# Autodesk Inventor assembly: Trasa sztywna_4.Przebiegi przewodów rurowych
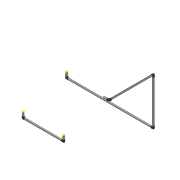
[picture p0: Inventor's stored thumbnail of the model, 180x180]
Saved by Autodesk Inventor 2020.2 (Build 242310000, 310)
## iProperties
ActiveState: False
BendRadius: UnInitValue
CouplingKey: v3#7e56b2cb-a132-4546-b8a7-a14538454b94#3
DefaultBendRadius: UnInitValue
Diameter: 1/2
DiameterType: Nominal
Elbow45Key: v3#a96c5204-26e4-4bb2-b8f1-f0623fbc94bb#2
Elbow90Key: v3#b72bb08b-ad33-47cc-a03d-7f3d76c6616b#3
ElbowCustomKey: UnInitValue
EndFittingKey: UnInitValue
Ending: UnInitValue
FittingMaterial: UnInitValue
FittingStandard: UnInitValue
FlangeKey: UnInitValue
Gap: UnInitValue
GasketKey: UnInitValue
ID: UnInitValue
IntermediateSegmentsInc: 2,540 mm
IntermediateSegmentsMax: 5080,000 mm
IntermediateSegmentsMin: 50,800 mm
IsButtWelded: False
IsFlanged: False
IsSelfDraining: False
Material: UnInitValue
MixedUnits: False
Name: ISO 7598/ISO 49 - Rury stalowe gwintowane ze stalowymi łącznikami
OD: UnInitValue
PipeKey: v3#1052637f-74b5-47f4-adeb-d4e8d3fa53b8#1
PipeType: Rigid Pipe
PipingComponentColor: As Material
RoundUpValue: UnInitValue
RouteDirection45: True
RouteDirection90: True
Schedule: ID=16.1
ShowGap: UnInitValue
Standard: UnInitValue
StartFittingKey: UnInitValue
SuppressEndFitting: UnInitValue
SuppressStartFitting: UnInitValue
TerminationSegmentsInc: 2,540 mm
TerminationSegmentsMax: 5080,000 mm
TerminationSegmentsMin: 50,800 mm
UseFlangsForCouplings: UnInitValue
UseSubASM: UnInitValue
_ComponentInfo: <CS><C N="Pipe" R="1.065000" IR="0.805000" PL="PL" PN="ISO 7598 Tube with Threaded Ends DN15"><CO N="1"><FE V="0"/><FD V="1"/><ET V="Threaded"/><NS V="1/2"/><MA
CouplingKey: UnInitValue
Diameter: 6
Elbow90Key: v3#97ecdcaf-8aa3-4fb0-8b6a-3da783de2ad5#108
Gap: 1,575 mm
IntermediateSegmentsInc: 0.00001 in
IntermediateSegmentsMin: 76,200 mm
IsButtWelded: True
Name: ASTM A 53/A-ASME B16.9 - Rura stalowa ze szwem
PipeKey: v3#4ce5e9fa-6da0-4801-ac02-ee7a0fb518d6#77
RouteDirection45: False
Schedule: 40
ShowGap: True
TerminationSegmentsInc: 0.00001 in
TerminationSegmentsMin: 76,200 mm
_ComponentInfo: <CS><C N="Elbow90" ER="15.240000" S1="15.240000" S2="15.240000" D1="0.000000" D2="0.000000" PartType="fitting" SymKey="ELBW"><CO N="1"><FE V="2"/><FD V="0"/><ET
Angle: UnInitValue
BendRadius: 12,700 mm
Elbow45Key: UnInitValue
Elbow90Key: UnInitValue
ID: 1,27
IntermediateSegmentsInc: UnInitValue
IntermediateSegmentsMax: UnInitValue
IntermediateSegmentsMin: UnInitValue
IsButtWelded: UnInitValue
IsFlanged: UnInitValue
IsSelfDraining: UnInitValue
MixedUnits: UnInitValue
Name: Przewód hydrauliczny – bez złączek
OD: 2,2352
PipeKey: v3#d489867e-ac9b-47ea-b952-0a1b885f66be#4
PipeType: Flexible Hose
RoundUpValue: 3,175 mm
RouteDirection45: UnInitValue
RouteDirection90: UnInitValue
Schedule: ID=0.5
SuppressEndFitting: True
SuppressStartFitting: True
TerminationSegmentsInc: UnInitValue
TerminationSegmentsMax: UnInitValue
TerminationSegmentsMin: UnInitValue
UseSubASM: True
_ComponentInfo: <CS><C N="Pipe" R="1.117600" OR="1.117600" IR="0.635000" PL="PL" PartType="" SymKey="" PN="Parker Hydraulic Hose - No Skive 1/2"><CO N="1"><FE V="0"/><FD V="0"/
Diameter: M40
Elbow45Key: v3#97879d80-057e-491b-840b-74a9b3a7cf63#17
Elbow90Key: v3#ace818b0-7b7c-4ad9-b19c-6da358a202c1#17
IntermediateSegmentsInc: 1,000 mm
IntermediateSegmentsMax: 5000,000 mm
IntermediateSegmentsMin: 60,000 mm
Name: DIN 2458/DIN 2605 - Rury stalowe spawane i łączniki
PipeKey: v3#dcef2839-8903-4c98-a96c-b861f5d9bb7f#98
Schedule: ID=30.7
TerminationSegmentsInc: 1,000 mm
TerminationSegmentsMax: 5000,000 mm
TerminationSegmentsMin: 60,000 mm
_ComponentInfo: <CS><C N="Pipe" R="2.415000" IR="1.535000" PL="PL" PN="DIN 2458 Pipe 48.3 x 8.8"><CO N="1"><FE V="2"/><FD V="0"/><ET V="Welded"/><NS V="M40"/><MA V="0.000000"/>
USE_R9_BOM: False
Angle: 92,00 deg
Diameter: 1
Elbow45Key: v3#bf26aa2a-f3dd-474c-8758-922a145c2b02#15
Elbow90Key: v3#3e93288f-9bb7-4e46-9d6b-544f8c20ca1c#3
ElbowCustomKey: v3#1f3bd44a-47ab-42f9-b3e0-74afa0c3f0ca#3
Gap: 2,388 mm
IsSelfDraining: True
Name: ASME BPE - Rura stalowa kołnierzowa
PipeKey: v3#b10c956f-6fc6-429e-8056-0864a8581764#35
Schedule: ID=0.87
_ComponentInfo: <CS><C N="Pipe" R="1.270000" OR="1.270000" IR="1.104900" PL="PL" PartType="pipe" SymKey="" PN="ASTM A 269 Tube with Welded ends 1 x 0.87"><CO N="1"><FE V="2"/><
CouplingKey: v3#181262db-c004-4877-bc40-c64b931a44f6#3
Elbow45Key: v3#960407aa-00b9-4d72-aae7-d50595845cfd#3
Elbow90Key: v3#6c92b367-65e9-486b-b952-db434ae2548d#3
IntermediateSegmentsMin: 20,000 mm
Name: JIS G 3442/JIS B 2301 - Rury stalowe gwintowane ze stalowymi łącznikami
PipeKey: v3#9964fba4-9d5a-4d75-85a8-e38022ccdce1#2
TerminationSegmentsMin: 20,000 mm
_ComponentInfo: <CS><C N="Pipe" R="1.085000" IR="0.805000" PL="PL" PN="JIS G 3442 Pipe with Threaded Ends 21.7 x 2.8"><CO N="1"><FE V="0"/><FD V="1"/><ET V="Threaded"/><NS V="1
EndFittingKey: v3#cc3bd835-95a2-497d-9893-176cd9c426f6#7
Name: Przewód hydrauliczny – gwint stożkowy wewnętrzny
StartFittingKey: v3#cc3bd835-95a2-497d-9893-176cd9c426f6#7
SuppressEndFitting: False
SuppressStartFitting: False
CouplingKey: v3#3edf83e2-464b-4b31-84c5-c329ffbf2a4f#5
Elbow45Key: v3#2f597a97-b15b-49d4-87cb-7bfe69eb62ee#5
Elbow90Key: v3#fbd68fd5-590c-4cb5-8c20-9e9bdd396a04#5
Name: DIN 8062/DIN 8063 - Rury i złączki PCV-U
PipeKey: v3#3d294dc7-89c3-4c37-a0ae-28c15a73bfd0#13
Schedule: 5
_ComponentInfo: <CS><C N="Pipe" R="2.000000" IR="1.700000" PL="PL" PN="DIN 8062 Pipe 40 x 3"><CO N="1"><FE V="0"/><FD V="0"/><ET V="Jointed"/><NS V="M40"/><MA V="8.000000"/><MI
CouplingKey: v3#52ad3977-2b89-4007-a6a6-7626bac0ae85#4
Elbow45Key: v3#5c2ab816-abcb-49a6-a106-4733af000f51#4
Elbow90Key: v3#160eac10-3e6f-4b5c-839c-61eee0d373dc#4
Name: ASME B36.10M-ASME B16.11 - Rury stalowe gwintowane
PipeKey: v3#4a736116-503a-44ad-a922-868ac6b46736#1
Schedule: 30
_ComponentInfo: <CS><C N="Pipe" R="1.066800" IR="0.825500" PL="PL" PN="ASME B36.10M Pipe with Threaded Ends 1/2 - Schedule 30"><CO N="1"><FE V="0"/><FD V="1"/><ET V="Threaded"/
Manager: www.cadconsulting.pl
Company: Fabian Stasiak CAD Consulting
CouplingKey: v3#eaa8de87-dc67-4eca-ba7e-4267a30f8f7f#2
Elbow45Key: v3#2769403e-a4fd-4a4c-8e4c-659ea845bd78#2
Elbow90Key: v3#c4513a61-3106-4a78-baf9-a1badd100245#2
IntermediateSegmentsMax: 2500,000 mm
Name: JIS K 6741/JIS K 6739 - Rury i złączki PCV-U
PipeKey: v3#45338dd0-af69-48c0-a2ed-8ade33a08701#5
Schedule: VP
TerminationSegmentsMax: 2500,000 mm
_ComponentInfo: <CS><C N="Pipe" R="2.400000" IR="2.040000" PL="PL" PN="JIS K 6741 Pipe VP 40"><CO N="1"><FE V="0"/><FD V="1"/><ET V="Jointed"/><NS V="M40"/><MA V="4.000000"/><M
EndFittingKey: v3#c5e461f5-5e73-4f2e-8c1e-4358d4d6f46c#4
Name: Przewód hydrauliczny – gwint wewnętrzny - obrotowy
StartFittingKey: v3#c5e461f5-5e73-4f2e-8c1e-4358d4d6f46c#4
EndFittingKey: v3#b50cb43e-68c0-48ac-8e25-7ef224ce0e6c#3
Name: Przewód hydrauliczny – gwint zewnętrzny prosty
StartFittingKey: v3#b50cb43e-68c0-48ac-8e25-7ef224ce0e6c#3
CouplingKey: v3#ed415c76-4cec-44a3-ba67-72e47bf70384#4
Elbow45Key: v3#2e5fd082-3851-4eb0-bde1-6c7078a7d72b#4
Elbow90Key: v3#82a08401-12d7-413b-b7f9-9cf3b607be7b#4
IntermediateSegmentsMin: 25,400 mm
Name: ASTM A53/A53M-ASME B16.11 - Rury stalowe spawane
PipeKey: v3#4ce5e9fa-6da0-4801-ac02-ee7a0fb518d6#7
TerminationSegmentsMin: 25,400 mm
_ComponentInfo: <CS><C N="Pipe" R="1.066800" IR="0.789940" PL="PL" PN="ASTM A 53/A 53M Pipe 1/2 - Schedule 40"><CO N="1"><FE V="0"/><FD V="0"/><ET V="Welded"/><NS V="1/2"/><MA 
ActiveState: True
CouplingKey: v3#12b64993-10e6-4915-8315-0c0cce209ad0#8
Elbow45Key: v3#28e76e79-e22c-40ab-8be2-ff545b1407c5#8
Elbow90Key: v3#1f65ece3-c41a-48d4-8661-909ed34ade86#8
Name: JIS G 3458/JIS B 2316 - Rury stalowe spawane i łączniki
PipeKey: v3#da14b0ab-0b36-4851-8d66-8c9cd0bcbe86#23
Schedule: 80
_ComponentInfo: <CS><C N="Pipe" R="2.430000" IR="1.920000" PL="PL" PN="JIS G 3458 Pipe 40 A x Sch 80"><CO N="1"><FE V="0"/><FD V="1"/><ET V="Welded"/><NS V="M40"/><MA V="0.0000
EndFittingKey: v3#933069c9-73b6-4141-af99-628d4a97b2c2#1
Name: Przewód hydrauliczny – złączki kołnierzowe SAE
StartFittingKey: v3#933069c9-73b6-4141-af99-628d4a97b2c2#1
Elbow90Key: v3#6a678020-d9d9-4685-bba9-906b9a167083#10
FlangeKey: v3#24991861-26e3-4c21-a713-f46e314eddd5#10
GasketKey: v3#2a41914c-f5fb-4682-9c6a-1870d826d3d0#23
IsFlanged: True
Name: ASTM A 53/A 53M - Rura stalowa kołnierzowa/spawana doczołowo
UseFlangsForCouplings: False
_ComponentInfo: <CS><C N="Pipe" R="8.413750" OR="8.413750" IR="7.702550" PL="PL" PartType="pipe" SymKey="" PN="ASTM A 53/A 53M Pipe 6 - Schedule 40"><CO N="1"><FE V="2"/><FD V=
Created: 2014-08
Part Number: Trasa sztywna_4.Przebiegi przewodów rurowych
Document SubType Name: Tube & Pipe
Designer: F.Stasiak
Manufacturer: Standard
Standards Organization: Custom
Catalog Web Link: www.expertbooks.pl
EndFittingKey: v3#c8250148-a7b6-458b-b7bd-3b56763ca7cc#13
Name: Przewód hydrauliczny – gwint stożkowy zewnętrzny
StartFittingKey: v3#c8250148-a7b6-458b-b7bd-3b56763ca7cc#13
FlangeKey: v3#c11442d2-c568-438f-a870-8ac9b5b636cb#10
Name: ASTM A 53/A-ASME B16.5 - Rura stalowa gwintowana kołnierzowa
PipeKey: v3#c5bd7d28-cdb3-4507-9f3d-c2787d93fe8a#40
_ComponentInfo: <CS><C N="Elbow90" ER="21.590000" S1="21.590000" S2="21.590000" D1="0.000000" D2="0.000000" PartType="fitting" SymKey="ELFL"><CO N="1"><FE V="2"/><FD V="1"/><ET
CouplingKey: v3#b06656e5-2b55-488c-bcf0-6a90c79c4683#2
Elbow45Key: v3#421a8b99-1721-409a-bc3b-c00889561754#1
Elbow90Key: v3#17490b17-1dd8-40fc-8de7-1a70c3bab2d7#1
IntermediateSegmentsMax: 2540,000 mm
Name: ISO 4065-ISO 3633 - Rury i złączki PCV
PipeKey: v3#4f84f716-5ba0-45ef-967a-c32c3d7345ce#70
Schedule: S40
TerminationSegmentsMax: 2540,000 mm
_ComponentInfo: <CS><C N="Pipe" R="2.000000" IR="1.950000" PL="PL" PN="ISO 4065 Pipe 40 x 0.5 S40"><CO N="1"><FE V="0"/><FD V="0"/><ET V="Jointed"/><NS V="M40"/><MA V="6.000000
CouplingKey: v3#771d4942-b9e7-43bc-9d41-ab12a9580492#3
Elbow45Key: v3#626cc28c-1a24-4045-be0d-40d896dc828d#3
Elbow90Key: v3#bc6b44ab-9235-4590-b699-74498030a1ff#3
Name: ANSI/ASME B36.19M-ASME B16.3 - Rury gwintowane ze stalowymi łącznikami
PipeKey: v3#323c0148-c750-449d-a0c6-11721f2a5046#1
Schedule: 40S
_ComponentInfo: <CS><C N="Pipe" R="1.066800" IR="0.789940" PL="PL" PN="ANSI/ASME B36.19M Pipe with Threaded Ends 1/2 - Schedule 40S"><CO N="1"><FE V="0"/><FD V="1"/><ET V="Thre
CouplingKey: v3#0dc1ae02-7bbf-4ccf-8498-581434b0a765#3
DefaultBendRadius: 50,800 mm
IntermediateSegmentsMin: 0,000 mm
Name: ASTM B 88-ASME B16.22 - Rury miedziane lutowane
PipeKey: v3#44b182c9-4bce-4825-bb4d-596143122252#7
PipeType: Tubing
Schedule: L
TerminationSegmentsMin: 0,000 mm
_ComponentInfo: <CS><C N="Pipe" R="0.793750" IR="0.692150" PL="PL" PN="ASTM B 88 Tube 1/2 - Type L"><CO N="1"><FE V="0"/><FD V="0"/><ET V="Soldered"/><NS V="1/2"/><MA V="2.5400
count: 53
Refkey_Axis1_Context: 2|0|0|0|1|0|0|0|
Refkey_Axis1: 6|0|0|0|44|0|0|0|78|0|65|0|77|0|69|0|83|0|10|0|67|0|111|0|108|0|111|0|114|0|115|0|10|0|49|0|58|0|10|0|10|0|69|0|78|0|68|0|10|0|0|0|
Refkey_Axis2_Context: 2|0|0|0|1|0|0|0|
Refkey_Axis2: 6|0|0|0|88|0|0|0|78|0|65|0|77|0|69|0|83|0|10|0|67|0|111|0|108|0|111|0|114|0|115|0|10|0|49|0|58|0|82|0|111|0|117|0|116|0|101|0|32|0|85|0|73|0|32|0|84|0|111|0|111
Refkey_Axis3_Context: 2|0|0|0|1|0|0|0|
Refkey_Axis3: 6|0|0|0|88|0|0|0|78|0|65|0|77|0|69|0|83|0|10|0|67|0|111|0|108|0|111|0|114|0|115|0|10|0|49|0|58|0|82|0|111|0|117|0|116|0|101|0|32|0|85|0|73|0|32|0|84|0|111|0|111
Refkey_Ext_Context: 2|0|0|0|1|0|0|0|
Refkey_Ext: 6|0|0|0|92|0|0|0|78|0|65|0|77|0|69|0|83|0|10|0|67|0|111|0|108|0|111|0|114|0|115|0|10|0|49|0|58|0|82|0|111|0|117|0|116|0|101|0|32|0|85|0|73|0|32|0|84|0|111|0|111
Refkey_Snap_Context: 2|0|0|0|1|0|0|0|
Refkey_Snap: 6|0|0|0|84|0|0|0|78|0|65|0|77|0|69|0|83|0|10|0|67|0|111|0|108|0|111|0|114|0|115|0|10|0|49|0|58|0|82|0|111|0|117|0|116|0|101|0|32|0|85|0|73|0|32|0|84|0|111|0|111
CouplingKey: v3#29993622-4c6a-437e-8b8c-43a0846f8735#1
Elbow45Key: v3#d7b5d569-4a12-4d65-ba55-12203d6ac7ed#1
Elbow90Key: v3#25d2a8db-6517-4627-a5a4-9d27e4d26b9b#1
Name: ASTM D 1785-ASTM D 2466 - Rury i złączki PCV
PipeKey: v3#4bf12049-4375-491b-8f13-d4ee0c517c57#1
_ComponentInfo: <CS><C N="Pipe" R="1.066800" IR="0.789940" PL="PL" PN="ASTM D 1785 Pipe 1/2 - Schedule 40"><CO N="1"><FE V="0"/><FD V="0"/><ET V="Jointed"/><NS V="1/2"/><MA V="
CouplingKey: v3#d2599e7a-1865-48da-a234-5418a1cd5dfe#3
Elbow45Key: v3#6ce5b1be-37aa-4928-b23a-0df64e6ddf38#2
Elbow90Key: v3#9fba244e-81ed-4fc6-a9ac-7eb372fa3ffe#3
Name: DIN 2458/DIN EN 10242 - Rury stalowe gwintowane i stalowe łączniki
PipeKey: v3#d689fd5f-ac5a-46d7-a883-3089b2f6e0a4#28
Schedule: ID=12.3
_ComponentInfo: <CS><C N="Pipe" R="1.065000" IR="0.615000" PL="PL" PN="DIN 2458 Pipe with Threaded Ends 21.3 x 4.5"><CO N="1"><FE V="0"/><FD V="1"/><ET V="Threaded"/><NS V="1/2
Author: F.Stasiak
Subject: Zbiór ćwiczeń. Autodesk Inventor 2020. Kurs Professional
Elbow45Key: v3#81684a3f-f2a4-4fe6-95b1-f067ddead22f#1
Elbow90Key: v3#451ae64e-c79d-4cba-b533-c09b8090ecb2#1
IntermediateSegmentsInc: 10,000 mm
IntermediateSegmentsMax: 9000,000 mm
IntermediateSegmentsMin: 1000,000 mm
Name: ISO 2531 - Rury żelazne kołnierzowe i łączniki
PipeKey: v3#f52fbdcb-ece8-4303-8b76-5dbe8c7f2f9c#16
Schedule: PN10
TerminationSegmentsInc: 10,000 mm
TerminationSegmentsMax: 9000,000 mm
TerminationSegmentsMin: 1000,000 mm
_ComponentInfo: <CS><C N="Pipe" R="2.700000" IR="2.000000" PL="PL" PN="ISO 2531 Pipe with Integrally Cast Flanges DN40 PN 10"><CO N="1"><FE V="0"/><FD V="0"/><ET V="Flanged"/><
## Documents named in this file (3)
- C:\2020_Kurs_Professional\R1 Rury\Trasa sztywna_4\AIP\Przewody rurowe\Trasa sztywna_4.Przebiegi przewodów rurowych.iam
- C:\2020_Kurs_Professional\R1 Rury\Trasa sztywna_4\AIP\Przewody rurowe\Przebieg01\Trasa sztywna_4.Przebieg01.iam
- C:\2020_Kurs_Professional\R1 Rury\Trasa sztywna_4\AIP\Przewody rurowe\Przebieg02\Trasa sztywna_4.Przebieg02.iam
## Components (2 placed, 2 different names)
1. Przebieg01 [sub-assembly]
2. Przebieg02 [sub-assembly]
